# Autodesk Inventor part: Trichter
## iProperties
Created: 2005-08
Part Number: Trichter
Material: 1.4301 X5CrNi18 10
Document SubType Name: Sheet Metal
Designer: grote
Manufacturer: Standard
Standards Organization: Custom
Author: grote
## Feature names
1. Erhebung1
2. Wandstärke1
3. Extrusion1
4. ExtrusionAbwicklung1
